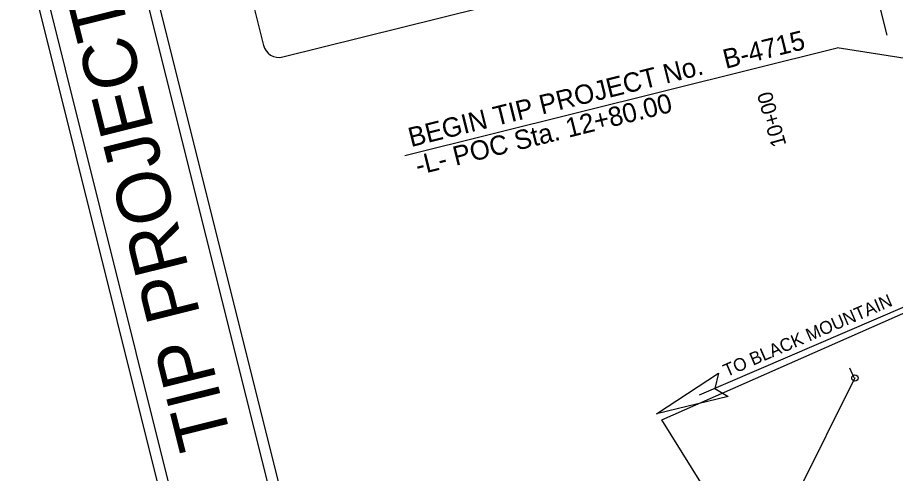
# Model space of a CAD drawing. Extents: x 1030323 to 1034123, y 654802 to 657751.
# Drawn here: x 1030543.2 to 1030952.4, y 656486.7 to 656699.4 of the extents above; entities that cross this region are included whole.
import ezdxf

# ---------------------------------------------------------------- set-up
doc = ezdxf.new("R2010")
doc.units = 0
for name, color, linetype in [('Old_Level_1', 7, 'Continuous'), ('Prop Horizontal Alignment Station Label', 7, 'Continuous'), ('Prop Horizontal Alignment Tick Label', 7, 'Continuous'), ('Prop Horizontal Alignment Tick Small', 7, 'Continuous'), ('Prop Terminator CELL', 7, 'Continuous'), ('Sheet Clip Boundary CELL', 7, 'Continuous'), ('Sheet Title CELL', 7, 'Continuous')]:
    doc.layers.add(name, color=color, linetype=linetype)

msp = doc.modelspace()

# ---------------------------------------------------------------- linework, layer by layer
at = {"layer": 'Old_Level_1'}
msp.add_line((1030956.64, 656564.48), (1030860.94, 656523.28), dxfattribs=at)
at = {"layer": 'Prop Horizontal Alignment Station Label'}
for p, q in [((1030723.76, 656635.04), (1030925.24, 656685.27)), ((1031188.45, 656644.42), (1030925.24, 656685.27)), ((1030933.53, 656531.26), (1030870.95, 656405.55))]:
    msp.add_line(p, q, dxfattribs=at)
msp.add_circle((1030933.53, 656531.26), 1.5, dxfattribs=at)
at = {"layer": 'Prop Horizontal Alignment Tick Small'}
msp.add_line((1030933.16, 656531.35), (1030931.12, 656535.91), dxfattribs=at)
msp.add_line((1030933.16, 656531.35), (1030931.12, 656535.91), dxfattribs=at)
at = {"layer": 'Prop Terminator CELL'}
msp.add_lwpolyline([(1030874.38, 656522.58), (1030841.08, 656514.57), (1030869.88, 656533.5), (1030868.29, 656526.28)], close=True, dxfattribs=at)
at = {"layer": 'Sheet Clip Boundary CELL'}
msp.add_lwpolyline([(1031088.75, 656293.37), (1030994.11, 656269.56), (1030843.5, 656511.74), (1030969.21, 656567.19), (1030968.58, 656775.34), (1031272.57, 656874.34), (1031522.82, 656933.1), (1031562.8, 656947.62), (1031759.53, 656972.55), (1031879.7, 656490.58)], close=True, dxfattribs=at)
at = {"layer": 'Sheet Title CELL'}
for p, q in [((1030750.07, 656141.07), (1030548.07, 656951.27)), ((1030789.97, 655960.36), (1030543.21, 656950.06)), ((1030597.29, 656929.11), (1030657.8, 656686.44)), ((1030666.87, 656681.06), (1030911.31, 656742.01))]:
    msp.add_line(p, q, dxfattribs=at)
for points in [[(1030948.53, 656691.15), (1030930.1, 656765.11), (1031721.05, 656962.31), (1031730.37, 656924.93)], [(1030493.49, 656942.81), (1030742.67, 655943.41)], [(1030499.56, 656939.18), (1030746.31, 655949.47)]]:
    msp.add_lwpolyline(points, dxfattribs=at)
msp.add_arc((1030665.05, 656688.34), 7.5, 194, 284, dxfattribs=at)

# ---------------------------------------------------------------- texts
at = {"layer": 'Old_Level_1'}
msp.add_text('TO BLACK MOUNTAIN', height=6, rotation=23.3185, dxfattribs=at).set_placement((1030873.73, 656531.63))
at = {"layer": 'Prop Horizontal Alignment Station Label'}
for s, p in [('BEGIN TIP PROJECT No.   B-4715', (1030726.62, 656638.96)), ('-L- POC Sta. 12+80.00', (1030729.88, 656625.86))]:
    msp.add_text(s, height=9, rotation=13.9833, dxfattribs=at).set_placement(p)
at = {"layer": 'Prop Horizontal Alignment Tick Label'}
msp.add_text('10+00', height=7, rotation=105.5824, dxfattribs=at).set_placement((1030901.61, 656640.13))
at = {"layer": 'Sheet Title CELL'}
msp.add_text('TIP PROJECT:', height=25, rotation=104, dxfattribs=at).set_placement((1030643.33, 656501.44))

doc.saveas('drawing.dxf')
